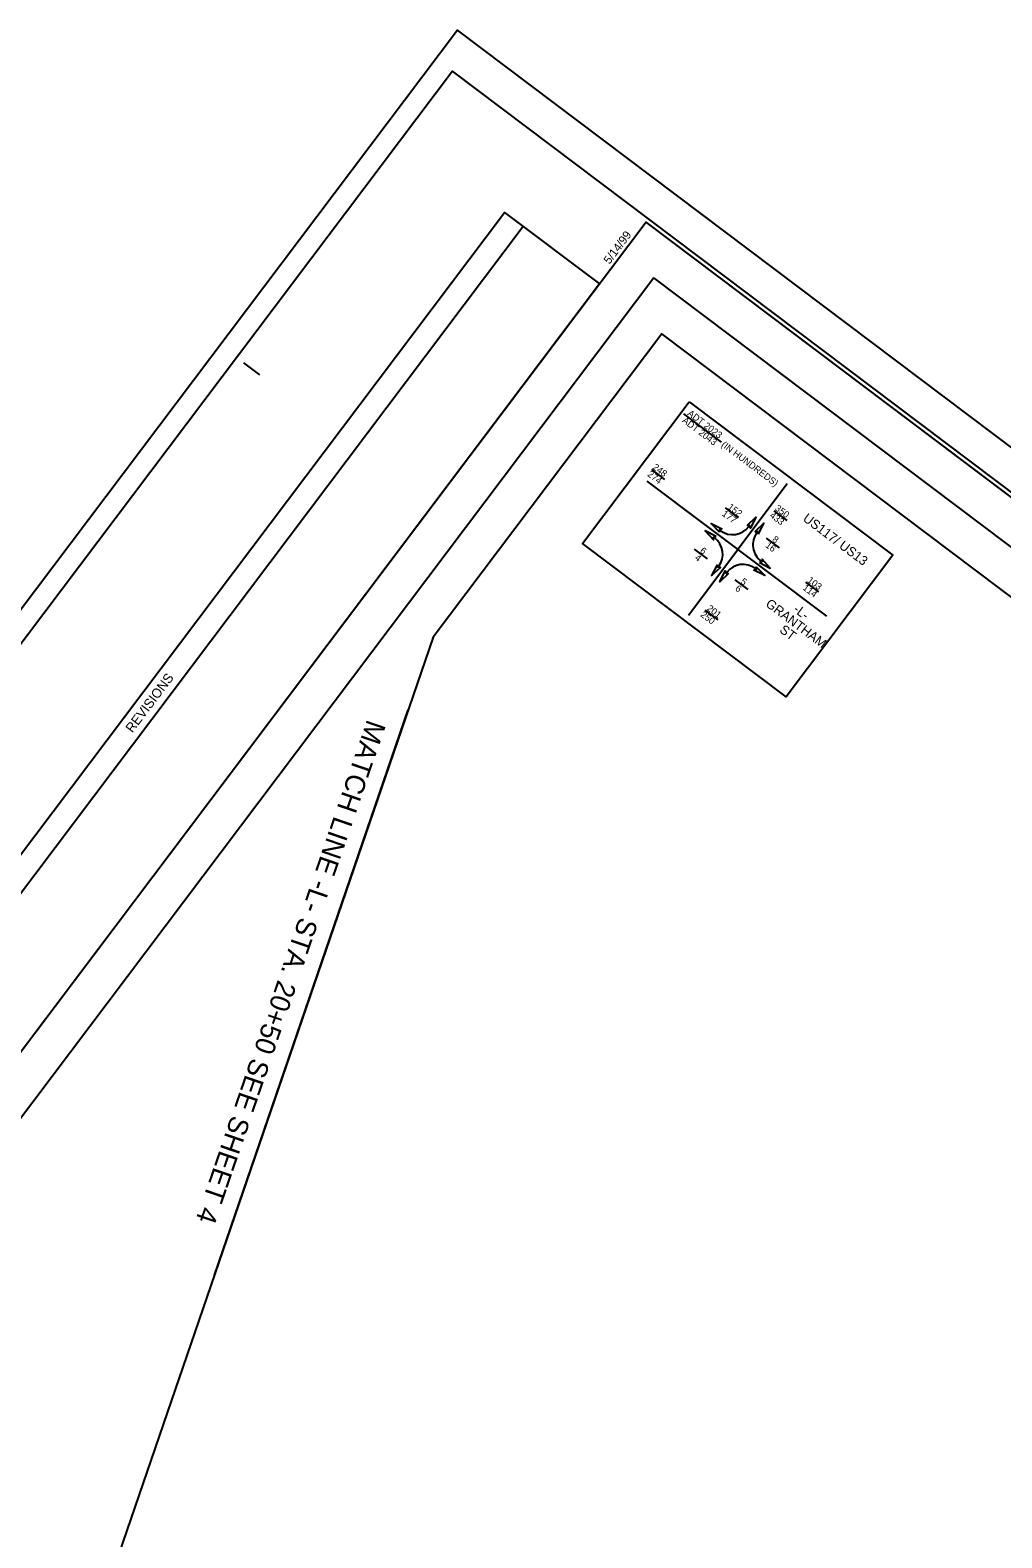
# Model space of a CAD drawing. Extents: x 2296955 to 2298159, y 600182 to 601317.
# Drawn here: x 2297191 to 2297557, y 600750 to 601317 of the extents above; entities that cross this region are included whole.
import ezdxf

# ---------------------------------------------------------------- set-up
doc = ezdxf.new("R2010")
doc.units = 0
for name, color, linetype in [('COGO Default Point Elevation', 7, 'Continuous'), ('COGO Default Point Number', 7, 'Continuous'), ('Default', 7, 'Continuous'), ('Exist DTM Drainline Cogo Comment', 7, 'Continuous'), ('Exist DTM Drainline Cogo Elevation', 7, 'Continuous'), ('Exist Property Iron Pin Cogo Number', 7, 'Continuous'), ('Exist Roads Curbs Cogo Number', 7, 'Continuous'), ('Exist Roads Curbs Cogo Point CELL', 7, 'Continuous'), ('Exist Roads EOP Cogo Comment', 7, 'Continuous'), ('Exist Roads EOP Cogo Elevation', 7, 'Continuous'), ('Exist Roads EOP Other Cogo Elevation', 7, 'Continuous')]:
    doc.layers.add(name, color=color, linetype=linetype)

msp = doc.modelspace()

# ---------------------------------------------------------------- linework, layer by layer
at = {"layer": 'COGO Default Point Elevation'}
msp.add_line((2297260.53, 600848.69), (2297333.49, 601061.53), dxfattribs=at)
at = {"layer": 'Default'}
for points in [[(2297449.34, 601126.82), (2297445.29, 601128.94), (2297448.4, 601125.58), (2297448.43, 601126.58)], [(2297450.6, 601128.39), (2297447.44, 601131.69), (2297451.53, 601129.63), (2297450.58, 601129.32)], [(2297461.03, 601130.91), (2297464.33, 601134.06), (2297462.27, 601129.97), (2297461.96, 601130.92)], [(2297465.25, 601127.73), (2297467.37, 601131.77), (2297464.01, 601128.66), (2297465.01, 601128.63)], [(2297465.7, 601117), (2297469.74, 601114.88), (2297466.64, 601118.25), (2297466.61, 601117.25)], [(2297449.79, 601116.1), (2297447.67, 601112.06), (2297451.03, 601115.16), (2297450.03, 601115.2)], [(2297454.06, 601112.88), (2297450.76, 601109.73), (2297452.82, 601113.82), (2297453.13, 601112.86)], [(2297464.49, 601115.4), (2297467.65, 601112.1), (2297463.56, 601114.16), (2297464.51, 601114.46)]]:
    msp.add_lwpolyline(points, close=True, dxfattribs=at)
for centre, start, end in [((2297455.56, 601135.2), 232.9992, 322.9992), ((2297444.15, 601120.17), 322.9991, 52.9991), ((2297470.88, 601123.65), 142.9991, 232.9991), ((2297459.53, 601108.59), 52.9992, 142.9992)]:
    msp.add_arc(centre, 7.69, start, end, dxfattribs=at)
at = {"layer": 'Exist DTM Drainline Cogo Comment'}
msp.add_lwpolyline([(2298148.7, 600700.2), (2297350.15, 601301.97), (2296969.16, 600796.39), (2297767.7, 600194.63)], close=True, dxfattribs=at)
at = {"layer": 'Exist DTM Drainline Cogo Elevation'}
for p, q in [((2297423.5, 601244.78), (2297423.5, 601244.78)), ((2297271.52, 601192.15), (2297277.51, 601187.63))]:
    msp.add_line(p, q, dxfattribs=at)
msp.add_lwpolyline([(2298141.78, 600703.5), (2297423.02, 601245.14), (2297043.87, 600742.01), (2297762.63, 600200.36)], close=True, dxfattribs=at)
at = {"layer": 'Exist Property Iron Pin Cogo Number'}
msp.add_lwpolyline([(2297342.87, 601088.91), (2297238.27, 600783.77), (2297197.22, 600664.01), (2297465.89, 600461.56), (2297631.65, 600336.65), (2298039.33, 600622.14), (2298039.33, 600622.14), (2297969.72, 600674.6), (2298027.87, 600751.78), (2297428.93, 601203.11)], close=True, dxfattribs=at)
at = {"layer": 'Exist Roads Curbs Cogo Number'}
msp.add_lwpolyline([(2297423.02, 601245.14), (2297043.89, 600742.01), (2297762.65, 600200.36), (2298069.63, 600607.76), (2297973.78, 600679.99), (2298045.93, 600775.73)], close=True, dxfattribs=at)
at = {"layer": 'Exist Roads Curbs Cogo Point CELL'}
msp.add_lwpolyline([(2298158.96, 600709.34), (2297352.03, 601317.42), (2296954.82, 600790.33), (2297761.75, 600182.24)], close=True, dxfattribs=at)
at = {"layer": 'Exist Roads EOP Cogo Comment'}
msp.add_lwpolyline([(2297425.97, 601224.13), (2297064.9, 600744.96), (2297759.7, 600221.37), (2298062.62, 600623.38), (2297966.76, 600695.61), (2298024.92, 600772.78)], close=True, dxfattribs=at)
at = {"layer": 'Exist Roads EOP Cogo Elevation'}
for p, q in [((2297437.09, 601173.04), (2297451.3, 601162.34)), ((2297425.02, 601151.97), (2297429.92, 601148.28)), ((2297423.34, 601147.67), (2297490.89, 601096.77)), ((2297476.15, 601146.58), (2297457.54, 601121.89)), ((2297452.8, 601137.57), (2297457.69, 601133.88)), ((2297471.04, 601136.49), (2297475.93, 601132.8)), ((2297468.19, 601126.18), (2297473.08, 601122.5)), ((2297438.94, 601097.2), (2297457.54, 601121.89)), ((2297441.13, 601122.08), (2297446.02, 601118.39)), ((2297456.36, 601110.48), (2297461.25, 601106.79)), ((2297482.99, 601109.62), (2297487.88, 601105.94)), ((2297445.06, 601099.11), (2297449.95, 601095.42))]:
    msp.add_line(p, q, dxfattribs=at)
msp.add_lwpolyline([(2297439.26, 601177.52), (2297515.91, 601119.76), (2297475.73, 601066.44), (2297399.08, 601124.2)], close=True, dxfattribs=at)
at = {"layer": 'Exist Roads EOP Other Cogo Elevation'}
msp.add_line((2297091.26, 600864.71), (2297376.75, 601243.57), dxfattribs=at)
msp.add_lwpolyline([(2297084.33, 600870.03), (2297369.77, 601248.81), (2297405.51, 601221.91), (2297120.07, 600843.12)], close=True, dxfattribs=at)

# ---------------------------------------------------------------- texts
at = {"layer": 'COGO Default Point Number'}
msp.add_text('MATCH LINE -L- STA. 20+50 SEE SHEET 4', height=7.5, rotation=251.0791, dxfattribs=at).set_placement((2297318.08, 601058.23))
at = {"layer": 'Exist DTM Drainline Cogo Elevation'}
msp.add_text('5/14/99', height=3.15, rotation=52.9991, dxfattribs=at).set_placement((2297409.23, 601229.09))
at = {"layer": 'Exist Roads EOP Cogo Elevation'}
for s, height, p in [('ADT 2023', 2.52, (2297438.35, 601172.67)), ('ADT 2043', 2.52, (2297436.37, 601170.03)), ('(IN HUNDREDS)', 2.52, (2297451.11, 601160.9)), ('274', 2.52, (2297423.29, 601149.76)), ('248', 2.52, (2297425.22, 601152.43)), ('177', 2.52, (2297451.33, 601134.9)), ('152', 2.52, (2297453.47, 601137.42)), ('433', 2.52, (2297469.3, 601134.28)), ('350', 2.52, (2297471.24, 601136.95)), ('US117/ US13', 3.528, (2297481.72, 601132.98)), ('16', 2.52, (2297467.69, 601123.04)), ('8', 2.52, (2297470.23, 601125.26)), ('4', 2.52, (2297441.11, 601118.32)), ('6', 2.52, (2297443.05, 601120.99)), ('6', 2.52, (2297456.29, 601106.76)), ('5', 2.52, (2297458.31, 601109.37)), ('114', 2.52, (2297481.73, 601107.05)), ('103', 2.52, (2297483.47, 601109.88)), ('201', 2.52, (2297445.66, 601099.28)), ('GRANTHAM', 3.528, (2297467.69, 601100.81)), ('-L-', 3.528, (2297478.12, 601098.74)), ('250', 2.52, (2297443.27, 601096.94)), (' ST', 3.528, (2297471.9, 601091.84))]:
    msp.add_text(s, height=height, rotation=322.9991, dxfattribs=at).set_placement(p)
at = {"layer": 'Exist Roads EOP Other Cogo Elevation'}
msp.add_text('REVISIONS', height=3.6, rotation=52.9991, dxfattribs=at).set_placement((2297229.67, 601052.66))

doc.saveas('drawing.dxf')
